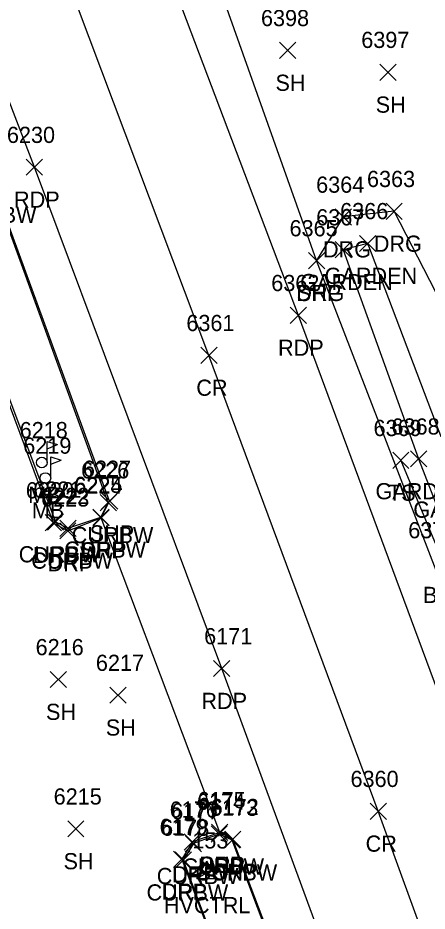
# Model space of a CAD drawing. Extents: x 1769141 to 1770911, y 735471 to 741449.
# Drawn here: x 1770248.9 to 1770299.5, y 740558.9 to 740669.3 of the extents above; entities that cross this region are included whole.
import ezdxf

# ---------------------------------------------------------------- set-up
doc = ezdxf.new("R2010")
doc.units = 0
for name, color, linetype in [('C_A', 7, 'Continuous'), ('C_I', 7, 'Continuous'), ('CPSM', 7, 'Continuous'), ('L_A', 7, 'Continuous'), ('L_I', 7, 'Continuous'), ('L_TIC', 7, 'Continuous'), ('LAPB', 7, 'Continuous'), ('LELB', 7, 'Continuous'), ('LMB', 7, 'Continuous'), ('P_A', 7, 'Continuous'), ('P_I', 7, 'Continuous'), ('P_TIC', 7, 'Continuous'), ('PET', 7, 'Continuous'), ('PRC', 7, 'Continuous'), ('PSP', 7, 'Continuous'), ('R_A', 7, 'Continuous'), ('R_I', 7, 'Continuous'), ('R_TIC', 7, 'Continuous'), ('RC', 7, 'Continuous'), ('RDG', 7, 'Continuous'), ('RDP', 7, 'Continuous')]:
    doc.layers.add(name, color=color, linetype=linetype)

msp = doc.modelspace()

# ---------------------------------------------------------------- linework, layer by layer
at = {"layer": 'CPSM'}
for p, q in [((1770271.02, 740562.94), (1770272.27, 740565.1)), ((1770273.52, 740562.94), (1770272.27, 740565.1)), ((1770272.27, 740563.66), (1770272.27, 740565.1)), ((1770271.02, 740562.94), (1770272.27, 740563.66)), ((1770272.27, 740563.66), (1770272.27, 740563.66)), ((1770272.27, 740563.66), (1770273.52, 740562.94)), ((1770271.02, 740562.94), (1770273.52, 740562.94))]:
    msp.add_line(p, q, dxfattribs=at)
at = {"layer": 'L_TIC'}
for points in [[(1770281.27, 740664.3), (1770283.27, 740666.3)], [(1770283.27, 740664.3), (1770281.27, 740666.3)], [(1770293.67, 740661.6), (1770295.67, 740663.6)], [(1770295.67, 740661.6), (1770293.67, 740663.6)], [(1770291.17, 740640.44), (1770293.17, 740642.44)], [(1770293.17, 740640.44), (1770291.17, 740642.44)], [(1770288.15, 740639.67), (1770290.15, 740641.67)], [(1770290.15, 740639.67), (1770288.15, 740641.67)], [(1770295.26, 740613.63), (1770297.26, 740615.63)], [(1770297.26, 740613.63), (1770295.26, 740615.63)], [(1770297.46, 740613.82), (1770299.46, 740615.82)], [(1770299.46, 740613.82), (1770297.46, 740615.82)], [(1770252.9, 740586.55), (1770254.9, 740588.55)], [(1770254.9, 740586.55), (1770252.9, 740588.55)], [(1770260.29, 740584.61), (1770262.29, 740586.61)], [(1770262.29, 740584.61), (1770260.29, 740586.61)], [(1770255.07, 740568.09), (1770257.07, 740570.09)], [(1770257.07, 740568.09), (1770255.07, 740570.09)]]:
    msp.add_lwpolyline(points, dxfattribs=at)
at = {"layer": 'LAPB'}
for points in [[(1770292.17, 740641.44), (1770289.15, 740640.67), (1770298.46, 740614.82), (1770311, 740582.54), (1770313.6, 740583.84), (1770304.8, 740608.27), (1770322.28, 740615.02), (1770320.99, 740618.23), (1770303.14, 740612.54)], [(1770303.14, 740612.54), (1770292.17, 740641.44)]]:
    msp.add_lwpolyline(points, dxfattribs=at)
at = {"layer": 'LELB'}
msp.add_lwpolyline([(1770296.26, 740614.63), (1770309.8, 740582.11)], dxfattribs=at)
at = {"layer": 'LMB'}
for p, q in [((1770252.52, 740616.97), (1770253.82, 740616.59)), ((1770252.53, 740614.38), (1770252.53, 740616.97)), ((1770252.53, 740616.07), (1770253.81, 740616.58)), ((1770252.96, 740615.05), (1770254.26, 740614.67)), ((1770252.97, 740612.46), (1770252.97, 740615.05)), ((1770252.97, 740614.15), (1770254.25, 740614.66)), ((1770251.87, 740614.37), (1770251.87, 740614.37)), ((1770252.31, 740612.45), (1770252.31, 740612.45))]:
    msp.add_line(p, q, dxfattribs=at)
for centre in [(1770251.87, 740614.37), (1770252.31, 740612.45)]:
    msp.add_circle(centre, 0.656, dxfattribs=at)
at = {"layer": 'P_TIC'}
for points in [[(1770249.94, 740649.86), (1770251.94, 740651.86)], [(1770251.94, 740649.86), (1770249.94, 740651.86)], [(1770284.85, 740638.32), (1770286.85, 740640.32)], [(1770286.85, 740638.32), (1770284.85, 740640.32)], [(1770282.59, 740631.55), (1770284.59, 740633.55)], [(1770284.59, 740631.55), (1770282.59, 740633.55)], [(1770271.53, 740626.61), (1770273.53, 740628.61)], [(1770273.53, 740626.61), (1770271.53, 740628.61)], [(1770259.25, 740608.6), (1770261.25, 740610.6)], [(1770261.25, 740608.6), (1770259.25, 740610.6)], [(1770258.2, 740606.52), (1770260.2, 740608.52)], [(1770260.2, 740606.52), (1770258.2, 740608.52)], [(1770273.11, 740587.9), (1770275.11, 740589.9)], [(1770275.11, 740587.9), (1770273.11, 740589.9)], [(1770292.48, 740570.26), (1770294.48, 740572.26)], [(1770294.48, 740570.26), (1770292.48, 740572.26)], [(1770272.86, 740567.65), (1770274.86, 740569.65)], [(1770274.86, 740567.65), (1770272.86, 740569.65)], [(1770274.49, 740566.79), (1770276.49, 740568.79)], [(1770276.49, 740566.79), (1770274.49, 740568.79)]]:
    msp.add_lwpolyline(points, dxfattribs=at)
at = {"layer": 'PET'}
for points in [[(1770379.16, 740373.29), (1770360.22, 740424.51), (1770338.77, 740482.71), (1770320.68, 740531.7), (1770305.06, 740574.76), (1770283.59, 740632.55), (1770262.08, 740689.36), (1770241.57, 740741.19), (1770220.78, 740793.37), (1770202.07, 740839.63), (1770179.17, 740893.09)], [(1770354.08, 740371.38), (1770337.26, 740416.85), (1770319.32, 740465.72), (1770304.61, 740505.64), (1770288.87, 740548.76), (1770274.11, 740588.9), (1770250.94, 740650.86), (1770225.28, 740717.64), (1770211.58, 740751.25), (1770191.43, 740801.9), (1770181.84, 740826.16)]]:
    msp.add_lwpolyline(points, dxfattribs=at)
at = {"layer": 'PRC'}
msp.add_lwpolyline([(1770366.94, 740369.74), (1770348.35, 740420.63), (1770327.06, 740479.58), (1770309.33, 740527.72), (1770293.48, 740571.26), (1770272.53, 740627.61), (1770250.4, 740686.41), (1770230.69, 740735.91), (1770209.56, 740788.44), (1770191.15, 740833.55), (1770180.86, 740858.33)], dxfattribs=at)
at = {"layer": 'PSP'}
for points in [[(1770540.34, 739951.65), (1770528.66, 739983.22), (1770504.99, 740047.85), (1770496.22, 740070.8), (1770481.82, 740111.56), (1770464.17, 740161.25), (1770449.88, 740201.4), (1770429.3, 740252.9), (1770418.04, 740283.83), (1770400.74, 740330.55), (1770384.34, 740374.74), (1770365.93, 740426.73), (1770363, 740434.14), (1770343.37, 740484.07), (1770326.57, 740533.85), (1770310.21, 740576.26), (1770285.85, 740639.32), (1770267.25, 740691.65), (1770245.28, 740742.42), (1770222.4, 740793.58), (1770203.84, 740840.26), (1770179.15, 740903.22)], [(1770346.98, 740368.28), (1770329.75, 740414.99), (1770313.12, 740462.55), (1770298.15, 740502.39), (1770298.12, 740506.76), (1770283.52, 740546.61), (1770275.49, 740567.79), (1770273.86, 740568.65), (1770259.2, 740607.52), (1770260.25, 740609.6), (1770245.76, 740649.04), (1770220.84, 740715.43), (1770204.69, 740758.31), (1770189.75, 740801.08), (1770182.17, 740816.05)]]:
    msp.add_lwpolyline(points, dxfattribs=at)
at = {"layer": 'R_TIC'}
for points in [[(1770294.43, 740644.41), (1770296.43, 740646.41)], [(1770296.43, 740644.41), (1770294.43, 740646.41)], [(1770288.15, 740643.71), (1770290.15, 740645.71)], [(1770290.15, 740643.71), (1770288.15, 740645.71)], [(1770284.85, 740638.32), (1770286.85, 740640.32)], [(1770286.85, 740638.32), (1770284.85, 740640.32)], [(1770259.09, 740608.4), (1770261.09, 740610.4)], [(1770261.09, 740608.4), (1770259.09, 740610.4)], [(1770252.28, 740605.93), (1770254.28, 740607.93)], [(1770254.28, 740605.93), (1770252.28, 740607.93)], [(1770252.55, 740606.02), (1770254.55, 740608.02)], [(1770254.55, 740606.02), (1770252.55, 740608.02)], [(1770258.18, 740606.6), (1770260.18, 740608.6)], [(1770260.18, 740606.6), (1770258.18, 740608.6)], [(1770258.2, 740606.52), (1770260.2, 740608.52)], [(1770260.2, 740606.52), (1770258.2, 740608.52)], [(1770254.09, 740604.92), (1770256.09, 740606.92)], [(1770256.09, 740604.92), (1770254.09, 740606.92)], [(1770254.1, 740605.24), (1770256.1, 740607.24)], [(1770256.1, 740605.24), (1770254.1, 740607.24)], [(1770272.79, 740567.44), (1770274.79, 740569.44)], [(1770274.79, 740567.44), (1770272.79, 740569.44)], [(1770272.86, 740567.65), (1770274.86, 740569.65)], [(1770274.86, 740567.65), (1770272.86, 740569.65)], [(1770269.48, 740566.47), (1770271.48, 740568.47)], [(1770271.48, 740566.47), (1770269.48, 740568.47)], [(1770269.61, 740566.26), (1770271.61, 740568.26)], [(1770271.61, 740566.26), (1770269.61, 740568.26)], [(1770274.41, 740566.7), (1770276.41, 740568.7)], [(1770276.41, 740566.7), (1770274.41, 740568.7)], [(1770268.17, 740564.33), (1770270.17, 740566.33)], [(1770270.17, 740564.33), (1770268.17, 740566.33)], [(1770268.36, 740564.23), (1770270.36, 740566.23)], [(1770270.36, 740564.23), (1770268.36, 740566.23)]]:
    msp.add_lwpolyline(points, dxfattribs=at)
at = {"layer": 'RC'}
for points in [[(1770222.17, 740690.52), (1770237.26, 740650.3), (1770253.55, 740607.02), (1770255.1, 740606.24), (1770259.18, 740607.6), (1770260.09, 740609.4), (1770245.65, 740648.98)], [(1770297.88, 740506.69), (1770283.36, 740546.54), (1770275.41, 740567.7), (1770273.79, 740568.44), (1770270.61, 740567.26), (1770269.36, 740565.23), (1770278.92, 740539.73)]]:
    msp.add_lwpolyline(points, dxfattribs=at)
at = {"layer": 'RDG'}
msp.add_lwpolyline([(1770351.85, 740662.51), (1770325.53, 740653.99), (1770323.33, 740650.05), (1770331.65, 740625.75), (1770309.41, 740618.28), (1770295.43, 740645.41), (1770289.15, 740644.71), (1770285.85, 740639.32)], dxfattribs=at)
at = {"layer": 'RDP'}
for points in [[(1770231.87, 740521.7), (1770212.9, 740515.59), (1770209.69, 740561.92), (1770208.23, 740601.59), (1770205.85, 740650.74), (1770204.34, 740686.71), (1770221.92, 740690.38), (1770237.17, 740650.12), (1770253.28, 740606.93), (1770255.09, 740605.92), (1770259.2, 740607.52)], [(1770273.86, 740568.65), (1770270.48, 740567.47), (1770269.17, 740565.33), (1770278.8, 740539.72), (1770264.83, 740533.77), (1770242.23, 740525.52)]]:
    msp.add_lwpolyline(points, dxfattribs=at)

# ---------------------------------------------------------------- texts
at = {"layer": 'C_A'}
msp.add_text('HVCTRL', height=2, dxfattribs=at).set_placement((1770266.96, 740558.66))
at = {"layer": 'C_I'}
msp.add_text('153', height=2, dxfattribs=at).set_placement((1770270.47, 740566.66))
at = {"layer": 'L_A'}
for s, p in [('SH', (1770280.76, 740660.3)), ('SH', (1770293.16, 740657.6)), ('GARDEN', (1770283.82, 740635.67)), ('GARDEN', (1770286.84, 740636.44)), ('MB', (1770250.18, 740609.37)), ('GARDEN', (1770293.13, 740609.82)), ('TS', (1770294.67, 740609.63)), ('MB', (1770250.62, 740607.45)), ('GARDEN', (1770297.81, 740607.54)), ('BS', (1770299.01, 740597)), ('SH', (1770252.38, 740582.55)), ('SH', (1770259.78, 740580.61)), ('SH', (1770254.55, 740564.09))]:
    msp.add_text(s, height=2, dxfattribs=at).set_placement(p)
at = {"layer": 'L_I'}
for s, p in [('6398', (1770278.97, 740668.3)), ('6397', (1770291.37, 740665.6)), ('6366', (1770288.76, 740644.44)), ('6367', (1770285.8, 740643.67)), ('6218', (1770249.13, 740617.37)), ('6369', (1770292.89, 740617.63)), ('6368', (1770295.11, 740617.82)), ('6219', (1770249.57, 740615.45)), ('6370', (1770297.18, 740605)), ('6216', (1770251.1, 740590.55)), ('6217', (1770258.55, 740588.61)), ('6215', (1770253.33, 740572.09))]:
    msp.add_text(s, height=2, dxfattribs=at).set_placement(p)
at = {"layer": 'P_A'}
for s, p in [('RDP', (1770248.43, 740645.86)), ('SHP', (1770283.39, 740634.32)), ('RDP', (1770281.08, 740627.55)), ('CR', (1770270.97, 740622.61)), ('SHP', (1770257.79, 740604.6)), ('SHP', (1770256.73, 740602.52)), ('RDP', (1770271.6, 740583.9)), ('CR', (1770291.91, 740566.26)), ('SHP', (1770271.4, 740563.65)), ('SHP', (1770273.03, 740562.79))]:
    msp.add_text(s, height=2, dxfattribs=at).set_placement(p)
at = {"layer": 'P_I'}
for s, p in [('6230', (1770247.55, 740653.86)), ('6365', (1770282.5, 740642.32)), ('6362', (1770280.24, 740635.55)), ('6361', (1770269.74, 740630.61)), ('6227', (1770256.95, 740612.6)), ('6224', (1770255.89, 740610.52)), ('6171', (1770271.94, 740591.9)), ('6360', (1770290.04, 740574.26)), ('6175', (1770271.12, 740571.65)), ('6172', (1770272.75, 740570.79))]:
    msp.add_text(s, height=2, dxfattribs=at).set_placement(p)
at = {"layer": 'R_A'}
for s, p in [('CURBW', (1770241.11, 740643.98)), ('DRG', (1770292.92, 740640.41)), ('DRG', (1770286.64, 740639.71)), ('DRG', (1770283.34, 740634.32)), ('CURBW', (1770255.56, 740604.4)), ('CURBW', (1770254.64, 740602.6)), ('DRP', (1770256.69, 740602.52)), ('CURBW', (1770249.01, 740602.02)), ('DRP', (1770250.77, 740601.93)), ('CURBW', (1770250.56, 740601.24)), ('DRP', (1770252.58, 740600.92)), ('CURBW', (1770269.25, 740563.44)), ('CURBW', (1770270.87, 740562.7)), ('DRP', (1770271.35, 740563.65)), ('CURBW', (1770266.08, 740562.26)), ('DRP', (1770267.97, 740562.47)), ('CURBW', (1770264.82, 740560.23)), ('DRP', (1770266.66, 740560.33))]:
    msp.add_text(s, height=2, dxfattribs=at).set_placement(p)
at = {"layer": 'R_I'}
for s, p in [('6364', (1770285.79, 740647.71)), ('6363', (1770292.08, 740648.41)), ('6365', (1770282.5, 740642.32)), ('6226', (1770256.73, 740612.4)), ('6225', (1770255.87, 740610.6)), ('6224', (1770255.89, 740610.52)), ('6220', (1770249.89, 740609.93)), ('6221', (1770250.81, 740610.02)), ('6222', (1770251.79, 740609.24)), ('6223', (1770251.78, 740608.92)), ('6175', (1770271.12, 740571.65)), ('6176', (1770267.68, 740570.47)), ('6174', (1770271.05, 740571.44)), ('6173', (1770272.67, 740570.7)), ('6177', (1770267.87, 740570.26)), ('6179', (1770266.43, 740568.33)), ('6178', (1770266.62, 740568.23))]:
    msp.add_text(s, height=2, dxfattribs=at).set_placement(p)

doc.saveas('drawing.dxf')
